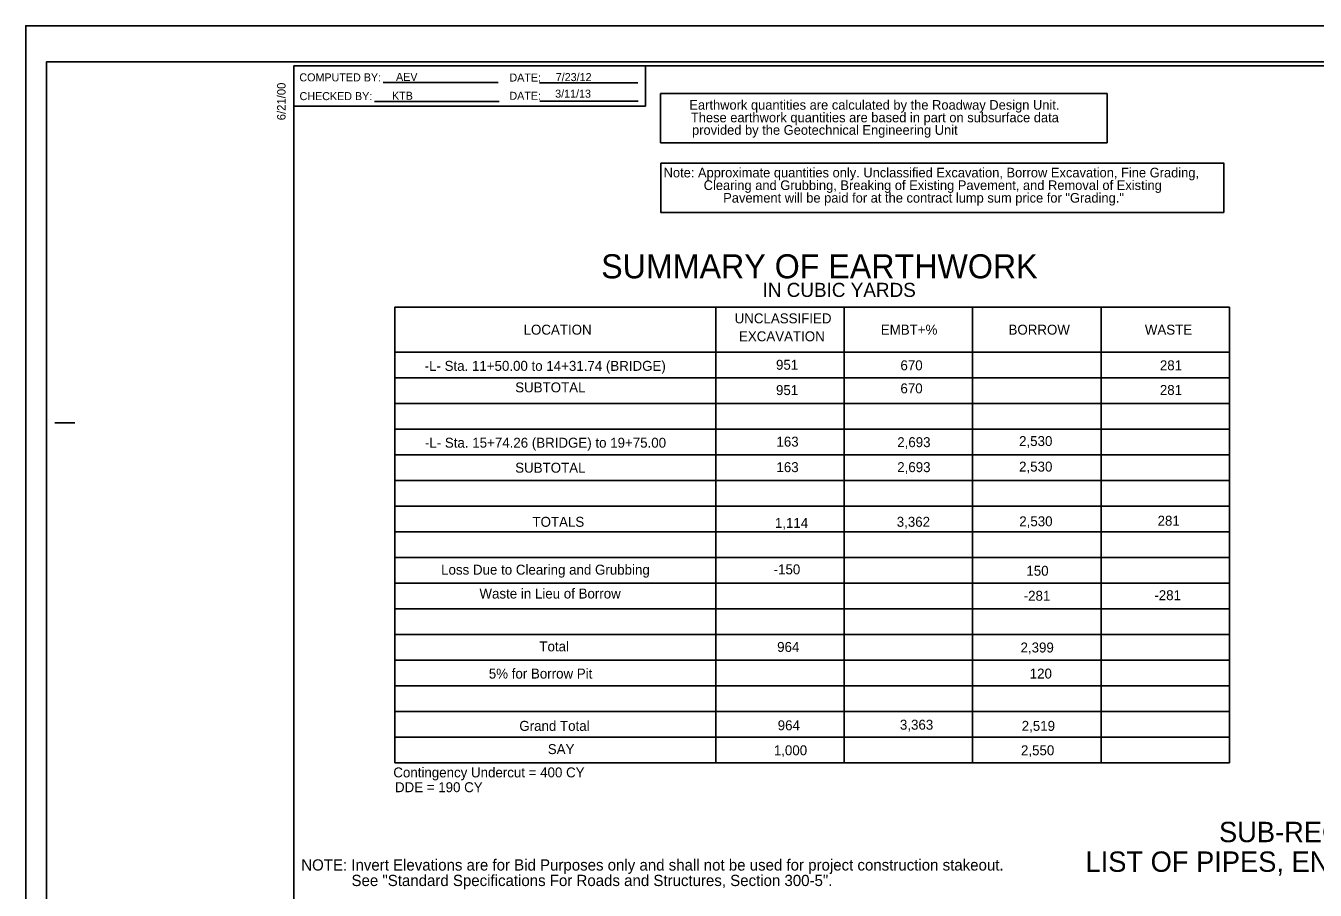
# Model space of a CAD drawing. Extents: x 576384 to 578068, y -52923 to -50483.
# Drawn here: x 576384 to 577187, y -52362 to -51823 of the extents above; entities that cross this region are included whole.
import ezdxf

# ---------------------------------------------------------------- set-up
doc = ezdxf.new("R2010")
doc.units = 0
for name, color, linetype in [('Prop Grid Mask', 7, 'Continuous'), ('Prop XSC Text', 7, 'Continuous'), ('Sheet Cutting Line CELL', 7, 'Continuous'), ('Sheet Data Field CELL', 7, 'Continuous'), ('Sheet Pipe Summary CELL', 7, 'Continuous'), ('Sheet Plot Border Inside CELL', 7, 'Continuous'), ('Sheet Plot Border Outside CELL', 7, 'Continuous'), ('Sheet Summary Combination CELL', 7, 'Continuous'), ('Sheet Summary Earthwork CELL', 7, 'Continuous')]:
    doc.layers.add(name, color=color, linetype=linetype)

msp = doc.modelspace()

# ---------------------------------------------------------------- linework, layer by layer
at = {"layer": 'Prop Grid Mask'}
for p, q in [((576778.91, -51865.48), (577057.26, -51865.48)), ((576778.91, -51896.23), (576778.91, -51865.48)), ((577057.26, -51865.48), (577057.26, -51896.23)), ((577057.26, -51896.23), (576778.91, -51896.23))]:
    msp.add_line(p, q, dxfattribs=at)
msp.add_lwpolyline([(576779.11, -51908.74), (577129.8, -51908.74), (577129.8, -51939.49), (576779.11, -51939.49)], close=True, dxfattribs=at)
at = {"layer": 'Sheet Cutting Line CELL'}
for p, q in [((578067.5, -51823.2), (576383.5, -51823.2)), ((576383.5, -51823.2), (576383.5, -52923.2))]:
    msp.add_line(p, q, dxfattribs=at)
at = {"layer": 'Sheet Plot Border Inside CELL'}
msp.add_lwpolyline([(578063, -51845.65), (576396.5, -51845.65), (576396.5, -52900.75), (578063, -52900.75)], close=True, dxfattribs=at)
at = {"layer": 'Sheet Plot Border Outside CELL'}
msp.add_lwpolyline([(578067.5, -51823.2), (576383.5, -51823.2), (576383.5, -52923.2), (578067.5, -52923.2)], close=True, dxfattribs=at)
at = {"layer": 'Sheet Summary Combination CELL'}
for p, q in [((576606.15, -51858.6), (576677.7, -51858.6)), ((576703.5, -51858.75), (576764.9, -51858.75)), ((576600.7, -51870.3), (576678.4, -51870.3)), ((576703.65, -51870.25), (576765.05, -51870.25)), ((576401.6, -52070.7), (576414.1, -52070.7))]:
    msp.add_line(p, q, dxfattribs=at)
for points in [[(578050.5, -51848.2), (576550.5, -51848.2), (576550.5, -52898.2), (578050.5, -52898.2)], [(576550.5, -51848.2), (576769.5, -51848.2), (576769.5, -51873.2), (576550.5, -51873.2)]]:
    msp.add_lwpolyline(points, close=True, dxfattribs=at)
at = {"layer": 'Sheet Summary Earthwork CELL'}
for p, q in [((576613.39, -52026.58), (577133.39, -52026.58)), ((576613.39, -52042.58), (577133.39, -52042.58)), ((577133.39, -52042.58), (577133.39, -52058.58)), ((576613.39, -52058.58), (577133.39, -52058.58)), ((576613.39, -52074.58), (577133.39, -52074.58)), ((576613.39, -52090.58), (577133.39, -52090.58)), ((576613.39, -52106.58), (577133.39, -52106.58)), ((576613.39, -52122.58), (576613.39, -52138.58)), ((576613.39, -52122.58), (577133.39, -52122.58)), ((576613.39, -52138.58), (577133.39, -52138.58)), ((577133.39, -52138.58), (577133.39, -52154.58)), ((577133.39, -52154.58), (576613.39, -52154.58)), ((577133.39, -52170.58), (576613.39, -52170.58)), ((576613.39, -52170.58), (576613.39, -52186.58)), ((576613.39, -52186.58), (577133.39, -52186.58)), ((577133.39, -52186.58), (577133.39, -52250.58)), ((576613.39, -52202.58), (577133.39, -52202.58)), ((576613.39, -52218.58), (577133.39, -52218.58)), ((576613.39, -52218.58), (576613.39, -52218.58)), ((576613.39, -52234.58), (577133.39, -52234.58)), ((577133.39, -52250.58), (576613.39, -52250.58)), ((576613.39, -52250.58), (577133.39, -52250.58)), ((577133.39, -52266.58), (576613.39, -52266.58)), ((577133.39, -52282.58), (576613.39, -52282.58))]:
    msp.add_line(p, q, dxfattribs=at)
for points in [[(576613.39, -52282.58), (576613.39, -51998.58), (577133.39, -51998.58)], [(576813.39, -52282.58), (576813.39, -51998.58), (576893.39, -51998.58), (576893.39, -52170.58)], [(576893.39, -52282.58), (576893.39, -51998.58), (576973.39, -51998.58), (576973.39, -52282.58)], [(577053.39, -52282.58), (577053.39, -51998.58), (577133.39, -51998.58), (577133.39, -52282.58)]]:
    msp.add_lwpolyline(points, dxfattribs=at)

# ---------------------------------------------------------------- texts
at = {"layer": 'Prop XSC Text'}
for s, p in [('Earthwork quantities are calculated by the Roadway Design Unit.', (576796.92, -51875.51)), ('These earthwork quantities are based in part on subsurface data', (576797.86, -51883.36)), ('provided by the Geotechnical Engineering Unit', (576798.57, -51891.14)), ('Note: Approximate quantities only. Unclassified Excavation, Borrow Excavation, Fine Grading, ', (576780.87, -51917.7)), ('Clearing and Grubbing, Breaking of Existing Pavement, and Removal of Existing ', (576805.82, -51925.56)), ('Pavement will be paid for at the contract lump sum price for "Grading."', (576818, -51933.43))]:
    msp.add_text(s, height=6, dxfattribs=at).set_placement(p)
at = {"layer": 'Sheet Data Field CELL'}
for s, p in [('AEV', (576614.16, -51857.55)), ('7/23/12', (576713.66, -51857.69)), ('KTB', (576611.66, -51869.31)), ('3/11/13', (576713.29, -51868))]:
    msp.add_text(s, height=5, dxfattribs=at).set_placement(p)
at = {"layer": 'Sheet Pipe Summary CELL'}
for s, height, p in [('SUB-REGIONAL & REGIONAL', 12.6999, (577126.87, -52332.04)), ('NOTE: Invert Elevations are for Bid Purposes only and shall not be used for project construction stakeout.', 7, (576555.1, -52349.71)), ('See "Standard Specifications For Roads and Structures, Section 300-5".', 7, (576586.43, -52359.38))]:
    msp.add_text(s, height=height, dxfattribs=at).set_placement(p)
at = {"layer": 'Sheet Summary Combination CELL'}
for s, height, p in [('COMPUTED BY:', 4.9998, (576553.95, -51857.85)), ('DATE:', 5, (576684.8, -51857.95)), ('CHECKED BY:', 4.9998, (576554.05, -51869.55)), ('DATE:', 5, (576684.8, -51869.35)), ('LIST OF PIPES, ENDWALLS, ETC. (FOR PIPES 48" & UNDER)', 12.6999, (577043.7, -52350.52))]:
    msp.add_text(s, height=height, dxfattribs=at).set_placement(p)
msp.add_text('6/21/00', height=5.25, rotation=90, dxfattribs=at).set_placement((576545.35, -51882.07))
at = {"layer": 'Sheet Summary Earthwork CELL'}
for s, height, p in [('SUMMARY OF EARTHWORK', 14.9999, (576741.98, -51980.62)), ('IN CUBIC YARDS', 8.7998, (576842.51, -51992.21)), ('UNCLASSIFIED', 6.1999, (576825.12, -52008.64)), ('LOCATION', 6.2, (576693.63, -52015.7)), ('EXCAVATION', 6.2, (576827.82, -52019.84)), ('EMBT+%', 6.2, (576916.19, -52015.7)), ('BORROW', 6.2, (576995.75, -52015.7)), ('WASTE', 6.2, (577080.67, -52015.7)), ('SUBTOTAL', 6.2, (576688.42, -52051.66)), ('SUBTOTAL', 6.2, (576688.42, -52101.74)), ('TOTALS', 6.2, (576699.16, -52135.47)), ('Loss Due to Clearing and Grubbing', 6.1999, (576642.27, -52165.28)), ('-150', 6.2, (576849.42, -52165.1)), ('150', 6.2, (577006.88, -52165.98)), ('Waste in Lieu of Borrow', 6.1999, (576666.13, -52180.17)), ('Total', 6.2, (576703.47, -52213.11)), ('5% for Borrow Pit', 6.1999, (576671.96, -52230.05)), ('Grand Total', 6.1999, (576690.97, -52262.64)), ('SAY', 6.2, (576708.71, -52277.14)), ('Contingency Undercut = 400 CY', 6.1999, (576612.48, -52291.65)), ('DDE = 190 CY', 6.1999, (576613.51, -52300.88))]:
    msp.add_text(s, height=height, rotation=360, dxfattribs=at).set_placement(p)
for s, height, p in [('-L- Sta. 11+50.00 to 14+31.74 (BRIDGE)', 6.1999, (576631.99, -52038.26)), ('951', 6.2, (576850.89, -52037.59)), ('670', 6.2, (576928.41, -52037.92)), ('281', 6.2, (577090.03, -52037.92)), ('670', 6.2, (576928.41, -52052.3)), ('951', 6.2, (576850.89, -52053.36)), ('281', 6.2, (577090.03, -52053.27)), ('-L- Sta. 15+74.26 (BRIDGE) to 19+75.00', 6.1999, (576632.16, -52086.16)), ('163', 6.2, (576851.16, -52085.49)), ('2,693', 6.2, (576926.41, -52085.83)), ('2,530', 6.2, (577002.32, -52085.14)), ('163', 6.2, (576851.16, -52101.39)), ('2,693', 6.2, (576926.41, -52101.39)), ('2,530', 6.2, (577002.32, -52101.04)), ('1,114', 6.2, (576850.2, -52136.15)), ('3,362', 6.2, (576926.09, -52135.46)), ('2,530', 6.2, (577002.43, -52135.13)), ('281', 6.2, (577088.61, -52134.78)), ('-281', 6.2, (577005.2, -52181.54)), ('-281', 6.2, (577086.58, -52181.2)), ('964', 6.2, (576851.6, -52213.44)), ('2,399', 6.2, (577003.22, -52213.79)), ('120', 6.2, (577008.94, -52230.04)), ('964', 6.2, (576851.95, -52262.3)), ('3,363', 6.2, (576928.1, -52261.94)), ('2,519', 6.2, (577003.96, -52262.63)), ('1,000', 6.2, (576849.53, -52277.86)), ('2,550', 6.2, (577003.51, -52277.86))]:
    msp.add_text(s, height=height, dxfattribs=at).set_placement(p)

doc.saveas('drawing.dxf')
